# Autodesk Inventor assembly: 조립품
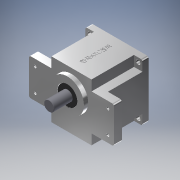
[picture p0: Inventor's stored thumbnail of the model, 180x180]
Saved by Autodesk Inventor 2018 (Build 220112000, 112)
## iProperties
Created: 2020-07
Part Number: 조립품
Material: 일반
Document SubType Name: Assembly
Designer: Admin
Author: Admin
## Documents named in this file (10)
- C:\Users\Admin\Desktop\700707V1005\조립품.iam
- C:\Users\Admin\Desktop\700707V1005\본체.ipt
- C:\Users\Admin\Desktop\700707V1005\커버.ipt
- C:\Users\Admin\Desktop\700707V1005\메인 축.ipt
- C:\Users\Admin\Desktop\700707V1005\서브 축.ipt
- C:\Users\Admin\Desktop\700707V1005\볼트 M4.ipt
- C:\Users\Admin\Desktop\700707V1005\베어링 6003.ipt
- C:\Users\Admin\Desktop\700707V1005\베어링 608.ipt
- C:\Users\Admin\Desktop\700707V1005\오일 실 17 32 8.ipt
- C:\Users\Admin\Desktop\700707V1005\오일 실 8 22 7.ipt
